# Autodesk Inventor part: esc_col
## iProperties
Shininess: 64.0
Length Units: 11269
Angle Units: 11279
Time Units: 11290
Mass Units: 11283
Length Display Precision: 3
Angle Display Precision: 2
Compacted: True
Part Number: esc_col
Document SubType Name: Modeling
Created: 2004-08
Designer: John Blackburn
Manufacturer: Standard
Standards Organization: Custom
Material: Lead
Density: 0.0
Volumn: 0.0
Area: 0.0
PropertySet Name: Model Information
Control State: 0
Master: False
Checked Out: False
Author: John Blackburn
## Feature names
1. Extrusion1
